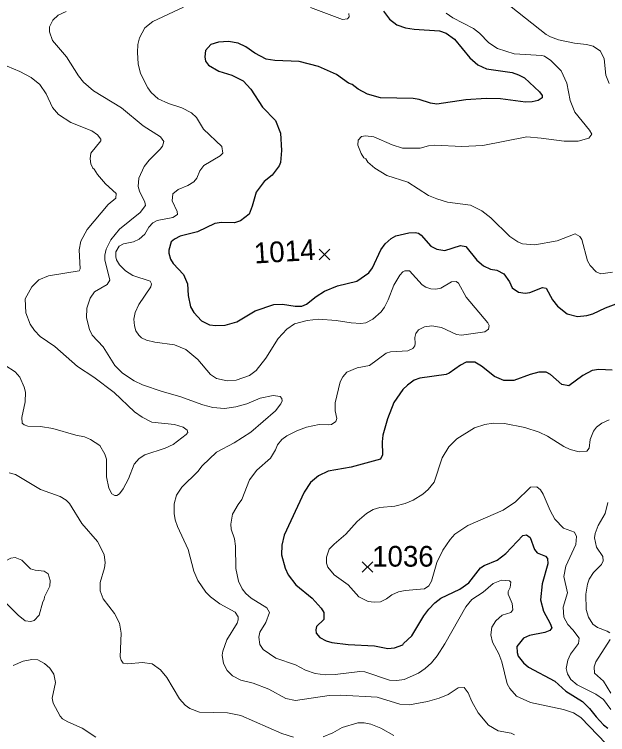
# Model space of a CAD drawing. Extents: x 265 to 291.4, y 7731.5 to 7759.6.
# Drawn here: x 274.669 to 276.962, y 7743.498 to 7746.284 of the extents above; entities that cross this region are included whole.
import ezdxf
from ezdxf.enums import TextEntityAlignment as Align

# ---------------------------------------------------------------- set-up
doc = ezdxf.new("R2010")
doc.units = 0
doc.header["$LTSCALE"] = 0.032
for name, color, linetype, lineweight in [('1', 7, 'Continuous', 25), ('2', 7, 'Continuous', 13), ('21', 7, 'Continuous', 25), ('61', 7, 'Continuous', 13)]:
    doc.layers.add(name, color=color, linetype=linetype, lineweight=lineweight)

msp = doc.modelspace()

# ---------------------------------------------------------------- linework, layer by layer
at = {"layer": '1'}
for points in [[(276.0961, 7746.2963), (276.1183, 7746.2653), (276.147, 7746.2438)], [(276.147, 7746.2438), (276.1804, 7746.2319), (276.2138, 7746.2263), (276.3125, 7746.2207), (276.3379, 7746.2112), (276.3705, 7746.1873), (276.4294, 7746.115)], [(276.4294, 7746.115), (276.4604, 7746.0887), (276.4939, 7746.0736), (276.5925, 7746.0585), (276.6179, 7746.0505), (276.6402, 7746.0378), (276.6991, 7745.9845), (276.7086, 7745.9702), (276.7086, 7745.9614), (276.6935, 7745.9503), (276.6705, 7745.9455), (276.645, 7745.9447), (276.5479, 7745.9574), (276.4923, 7745.959), (276.4143, 7745.9535), (276.3013, 7745.9367), (276.2775, 7745.9399), (276.2329, 7745.9551), (276.2107, 7745.959), (276.0834, 7745.9614), (276.0333, 7745.9749), (275.9975, 7745.9948), (275.9744, 7746.0123), (275.9609, 7746.0179), (275.9139, 7746.0513), (275.8447, 7746.0823), (275.77, 7746.1014), (275.6761, 7746.1054), (275.6427, 7746.111), (275.5981, 7746.134), (275.5639, 7746.1587), (275.5345, 7746.173), (275.4963, 7746.1786), (275.4581, 7746.1762), (275.4287, 7746.1675), (275.408, 7746.1436), (275.4048, 7746.1197), (275.4072, 7746.103), (275.4191, 7746.0879), (275.4597, 7746.064), (275.509, 7746.0489), (275.5536, 7746.0266), (275.583, 7745.994), (275.6275, 7745.9248), (275.6777, 7745.8739), (275.6976, 7745.8238), (275.7015, 7745.757), (275.6976, 7745.7109), (275.692, 7745.6981), (275.665, 7745.6623), (275.6339, 7745.6376), (275.6029, 7745.5955), (275.5886, 7745.5422), (275.5766, 7745.5112), (275.5432, 7745.4857), (275.5202, 7745.4778), (275.4693, 7745.4794), (275.4438, 7745.4754), (275.377, 7745.4428), (275.3102, 7745.4261), (275.2879, 7745.4149), (275.2752, 7745.4046), (275.2656, 7745.372), (275.2656, 7745.3608), (275.272, 7745.337), (275.2823, 7745.3203), (275.3229, 7745.2781), (275.338, 7745.2415), (275.3412, 7745.197), (275.3499, 7745.1524), (275.3626, 7745.1302), (275.3921, 7745.0983), (275.4231, 7745.0832), (275.447, 7745.0808), (275.4836, 7745.0824), (275.5281, 7745.0951), (275.5997, 7745.1373), (275.6713, 7745.1612), (275.7047, 7745.1635), (275.7541, 7745.1548), (275.7795, 7745.1548), (275.7986, 7745.1635), (275.8352, 7745.193), (275.8678, 7745.2137), (275.9179, 7745.2335), (275.9919, 7745.2518), (276.0388, 7745.2837), (276.0531, 7745.3036), (276.0857, 7745.3736), (276.1017, 7745.3966), (276.1255, 7745.4173), (276.1438, 7745.4269), (276.1932, 7745.4388), (276.2186, 7745.4404), (276.2313, 7745.4372)], [(276.2313, 7745.4372), (276.2417, 7745.4292), (276.2783, 7745.3879), (276.3013, 7745.3751), (276.3324, 7745.3704), (276.3936, 7745.3895), (276.4135, 7745.3855)], [(276.4135, 7745.3855), (276.4564, 7745.333), (276.4819, 7745.3115), (276.5098, 7745.2988), (276.5336, 7745.294), (276.5607, 7745.2805), (276.5821, 7745.2495), (276.5925, 7745.2264), (276.6179, 7745.2097), (276.6434, 7745.2049), (276.6609, 7745.2081), (276.7102, 7745.2272), (276.7237, 7745.2248), (276.7484, 7745.1795), (276.7683, 7745.1548), (276.8057, 7745.1262), (276.8455, 7745.1158), (276.8821, 7745.119), (276.9043, 7745.1254), (276.9536, 7745.1492), (277.0046, 7745.1675)], [(276.9791, 7744.9074), (276.9282, 7744.9106), (276.9027, 7744.9058), (276.8661, 7744.8867), (276.812, 7744.8469), (276.785, 7744.8517), (276.7412, 7744.8915), (276.7237, 7744.9002), (276.6959, 7744.9002), (276.6625, 7744.8915), (276.5989, 7744.8676), (276.5607, 7744.8676), (276.5241, 7744.8835), (276.4739, 7744.9233), (276.4485, 7744.9384), (276.4151, 7744.9384), (276.3936, 7744.9273), (276.3499, 7744.8963), (276.3379, 7744.8915), (276.2361, 7744.8772), (276.2146, 7744.8692), (276.1884, 7744.8501), (276.1709, 7744.8326), (276.1359, 7744.7833), (276.1112, 7744.7197), (276.0929, 7744.656), (276.0905, 7744.6306), (276.0921, 7744.5797), (276.0834, 7744.5629), (275.9704, 7744.5327), (275.8813, 7744.5176), (275.8439, 7744.4993), (275.8137, 7744.4731), (275.789, 7744.4365), (275.7119, 7744.2694), (275.7023, 7744.2313), (275.7015, 7744.1931), (275.7151, 7744.1422), (275.727, 7744.1167), (275.7564, 7744.0769), (275.8193, 7744.026), (275.8542, 7743.9878), (275.8654, 7743.9711), (275.8654, 7743.9441), (275.8368, 7743.917), (275.8336, 7743.9035), (275.8352, 7743.8908), (275.8495, 7743.8741), (275.8734, 7743.8605), (275.8957, 7743.8542)], [(276.1725, 7743.8502), (276.2051, 7743.8804), (276.2512, 7743.9576), (276.2703, 7743.9839), (276.2934, 7744.0085), (276.3173, 7744.026), (276.3904, 7744.061), (276.4254, 7744.0857), (276.4708, 7744.143), (276.4843, 7744.1525), (276.5352, 7744.1724), (276.5686, 7744.1986), (276.6346, 7744.2678), (276.6482, 7744.271), (276.6625, 7744.2607), (276.679, 7744.2143), (276.6896, 7744.2011), (276.7221, 7744.1884), (276.7301, 7744.1791), (276.7308, 7744.1592), (276.7094, 7744.0817), (276.7022, 7744.0197), (276.7134, 7743.9751), (276.7404, 7743.9274), (276.746, 7743.9115), (276.7388, 7743.9003), (276.7198, 7743.8931), (276.6593, 7743.8812), (276.6362, 7743.8709), (276.6116, 7743.8391), (276.6124, 7743.816), (276.6163, 7743.8017), (276.6362, 7743.7754), (276.6561, 7743.7587), (276.758, 7743.7054), (276.8009, 7743.6664), (276.8646, 7743.6267), (276.8924, 7743.5996), (276.917, 7743.567), (276.9457, 7743.536), (276.9632, 7743.5233)], [(275.8957, 7743.8542), (275.9593, 7743.847), (276.0611, 7743.8422), (276.112, 7743.8319), (276.1375, 7743.8343), (276.1709, 7743.8454), (276.1725, 7743.8502)]]:
    msp.add_lwpolyline(points, dxfattribs=at)
at = {"layer": '2'}
for points in [[(275.3229, 7746.3114), (275.2036, 7746.2566), (275.1733, 7746.2311), (275.1527, 7746.1929), (275.1463, 7746.1675), (275.1447, 7746.1357), (275.1479, 7746.0927), (275.1558, 7746.0545), (275.1845, 7745.9996), (275.1972, 7745.9813), (275.2243, 7745.9567), (275.264, 7745.9392), (275.3165, 7745.9225), (275.3539, 7745.9034), (275.3722, 7745.8843), (275.4, 7745.8397), (275.4701, 7745.7721), (275.474, 7745.7467), (275.4645, 7745.7363), (275.4016, 7745.6997), (275.3857, 7745.679), (275.3738, 7745.6504), (275.3619, 7745.6361), (275.3396, 7745.6218), (275.3022, 7745.6066), (275.2807, 7745.5891), (275.2791, 7745.5629), (275.2982, 7745.5215), (275.299, 7745.5096), (275.2815, 7745.4977), (275.2211, 7745.4865), (275.2036, 7745.4778), (275.1892, 7745.4611), (275.1725, 7745.434), (275.1511, 7745.4141), (275.1288, 7745.4046), (275.0906, 7745.3958), (275.0739, 7745.3871), (275.0612, 7745.3656), (275.0604, 7745.3465), (275.0636, 7745.3338), (275.0747, 7745.3147), (275.0978, 7745.2916), (275.1272, 7745.2741), (275.1932, 7745.2519), (275.1988, 7745.2415), (275.1964, 7745.2296), (275.1503, 7745.162), (275.1359, 7745.1302), (275.1312, 7745.1047), (275.1328, 7745.0792), (275.1383, 7745.0602), (275.1495, 7745.0426), (275.1606, 7745.0331), (275.1797, 7745.0236), (275.2115, 7745.0156), (275.2879, 7745.0053), (275.3316, 7744.9878), (275.3786, 7744.9496), (275.4271, 7744.8915), (275.4502, 7744.8756), (275.4915, 7744.866), (275.5265, 7744.8692), (275.5775, 7744.8867), (275.6037, 7744.9058), (275.6411, 7744.9536), (275.688, 7745.0299), (275.7222, 7745.0657), (275.7517, 7745.0864), (275.8002, 7745.0999), (275.8447, 7745.1047), (275.9132, 7745.0999), (275.9704, 7745.0904), (276.0086, 7745.0888), (276.0277, 7745.0912), (276.0547, 7745.1055), (276.0866, 7745.1333), (276.0993, 7745.1508), (276.1136, 7745.1795)], [(275.9617, 7746.2868), (275.9625, 7746.2741), (275.9561, 7746.2661), (275.937, 7746.2645), (275.8129, 7746.3106)], [(276.5885, 7746.313), (276.7245, 7746.2064), (276.7405, 7746.1969), (276.7723, 7746.1858), (276.8343, 7746.173), (276.8805, 7746.1675), (276.9059, 7746.1603), (276.9338, 7746.142), (276.9481, 7746.1118), (276.9552, 7746.0481), (276.9679, 7746.0163)], [(275.4629, 7744.0045), (275.4263, 7744.0308), (275.4088, 7744.0491), (275.3786, 7744.0944), (275.3627, 7744.131), (275.3404, 7744.2138), (275.299, 7744.3029), (275.2903, 7744.3283), (275.2863, 7744.3538), (275.2863, 7744.3904), (275.295, 7744.4238), (275.3157, 7744.4556), (275.3778, 7744.5152), (275.3945, 7744.5375), (275.4502, 7744.59), (275.5186, 7744.6266), (275.5822, 7744.668), (275.6785, 7744.7507), (275.6992, 7744.777), (275.7039, 7744.7897), (275.7023, 7744.7984), (275.696, 7744.8064), (275.6697, 7744.8104), (275.6188, 7744.7992), (275.5679, 7744.777), (275.525, 7744.7658), (275.4804, 7744.7594), (275.4359, 7744.7634), (275.3977, 7744.7738), (275.3086, 7744.8064), (275.2402, 7744.8247), (275.1638, 7744.8509), (275.132, 7744.8668), (275.0874, 7744.8955), (275.0572, 7744.9257), (275.0119, 7744.9981), (274.9697, 7745.0434), (274.9586, 7745.0649), (274.9474, 7745.1095), (274.949, 7745.1477), (274.9617, 7745.1858), (274.9784, 7745.2113), (275.0278, 7745.2391), (275.0381, 7745.2558), (275.019, 7745.3338), (275.019, 7745.3529), (275.0238, 7745.3759), (275.0413, 7745.4118), (275.0747, 7745.4531), (275.155, 7745.5175), (275.1757, 7745.5446), (275.1733, 7745.5573), (275.1519, 7745.5995), (275.1479, 7745.6186), (275.1495, 7745.6504), (275.171, 7745.695), (275.19, 7745.7196), (275.233, 7745.7618), (275.2418, 7745.7745), (275.2465, 7745.792), (275.2338, 7745.8103), (275.167, 7745.8532), (275.0827, 7745.9225), (274.9753, 7745.9877), (274.9363, 7746.0219), (274.9164, 7746.0466), (274.8703, 7746.1197), (274.8162, 7746.1826), (274.8042, 7746.2168), (274.805, 7746.2359), (274.817, 7746.2613), (274.8384, 7746.2812), (274.8695, 7746.2947)], [(276.3427, 7745.5573), (276.3013, 7745.57), (276.2695, 7745.5836), (276.19, 7745.6353), (276.1088, 7745.6607), (276.0627, 7745.6886), (276.0356, 7745.7124), (276.0277, 7745.7244), (276.0197, 7745.7291), (276.0094, 7745.7459), (275.9967, 7745.7777), (275.9975, 7745.7976), (276.011, 7745.8111), (276.0261, 7745.8143), (276.0579, 7745.8103), (276.1287, 7745.7793), (276.1693, 7745.7665), (276.2377, 7745.7665), (276.2695, 7745.7753), (276.2934, 7745.7777), (276.3984, 7745.7729), (276.4795, 7745.7761), (276.6498, 7745.8095), (276.7055, 7745.8055), (276.7945, 7745.7936), (276.8486, 7745.7928), (276.8892, 7745.8055), (276.9003, 7745.8206), (276.8916, 7745.8365), (276.8351, 7745.905), (276.8168, 7745.9511), (276.8041, 7746.0179), (276.7826, 7746.0656), (276.7428, 7746.1054), (276.7174, 7746.1221), (276.707, 7746.1253), (276.6004, 7746.1317), (276.5368, 7746.1516), (276.5026, 7746.1738), (276.4668, 7746.2104), (276.4429, 7746.2287), (276.3634, 7746.2701), (276.3379, 7746.2884)], [(274.6165, 7746.0943), (274.6897, 7746.0625), (274.7342, 7746.0394), (274.7677, 7746.0123), (274.7923, 7745.9766), (274.8162, 7745.9241), (274.8392, 7745.8962), (274.887, 7745.866), (274.9681, 7745.8334), (274.9904, 7745.8182), (275.0031, 7745.8007), (275.0031, 7745.7944), (274.9649, 7745.7466), (274.9617, 7745.7252), (274.9649, 7745.7053), (274.9721, 7745.6886), (274.9777, 7745.6846), (274.9896, 7745.6639), (275.0206, 7745.6289), (275.0628, 7745.5907), (275.0612, 7745.5732), (275.0318, 7745.5486), (274.9498, 7745.4515), (274.9251, 7745.407), (274.9188, 7745.3736), (274.9236, 7745.2996), (274.9196, 7745.2916), (274.8011, 7745.2725), (274.7629, 7745.2574), (274.7358, 7745.2304), (274.7112, 7745.1834), (274.7136, 7745.1294), (274.7295, 7745.0856), (274.7461, 7745.0617), (274.7684, 7745.0379), (274.8249, 7744.9989), (274.9124, 7744.9225), (274.9761, 7744.8804), (275.054, 7744.8215), (275.1336, 7744.7467)], [(276.6323, 7745.3966), (276.6148, 7745.4046), (276.5837, 7745.4253), (276.5106, 7745.4969), (276.4756, 7745.5239), (276.4318, 7745.5462), (276.3427, 7745.5573)], [(276.9807, 7745.2861), (276.9361, 7745.2805), (276.9178, 7745.2884), (276.894, 7745.3123), (276.8844, 7745.3306), (276.8622, 7745.4134), (276.8542, 7745.4245), (276.8359, 7745.4348), (276.7675, 7745.4078), (276.68, 7745.3927), (276.6323, 7745.3966)], [(276.1136, 7745.1795), (276.1351, 7745.2368), (276.1589, 7745.2749), (276.1709, 7745.2885), (276.178, 7745.2916), (276.1963, 7745.2916), (276.2449, 7745.2383)], [(276.2449, 7745.2383), (276.2592, 7745.2288), (276.2791, 7745.2224), (276.2982, 7745.2208), (276.3173, 7745.2248), (276.3586, 7745.2495), (276.3761, 7745.2503), (276.3849, 7745.2439), (276.4151, 7745.1906), (276.4986, 7745.0904), (276.5034, 7745.0808), (276.501, 7745.0657), (276.4875, 7745.0562), (276.3968, 7745.0426), (276.3777, 7745.0458), (276.3204, 7745.0721), (276.2823, 7745.0792), (276.2536, 7745.0753), (276.2305, 7745.0641), (276.2202, 7745.049), (276.217, 7745.0339), (276.2186, 7745.0108), (276.2162, 7745.0013), (276.209, 7744.9917), (276.19, 7744.983), (276.1232, 7744.9782), (276.1057, 7744.9734), (276.042, 7744.9257), (275.9943, 7744.9162), (275.9537, 7744.8995), (275.9386, 7744.8819), (275.9283, 7744.8629), (275.9084, 7744.7809), (275.9092, 7744.7499), (275.9147, 7744.7213), (275.9116, 7744.7093), (275.8941, 7744.6982), (275.8845, 7744.6958), (275.8463, 7744.6982), (275.7986, 7744.6871), (275.7604, 7744.6727), (275.7222, 7744.6536), (275.7031, 7744.6393), (275.6856, 7744.6187), (275.6785, 7744.5996), (275.6594, 7744.567), (275.6061, 7744.5208), (275.5774, 7744.4842), (275.548, 7744.4079), (275.5337, 7744.3888), (275.5122, 7744.3506), (275.5059, 7744.3124), (275.5074, 7744.2933), (275.5194, 7744.2551), (275.5241, 7744.2265), (275.5249, 7744.1406), (275.5353, 7744.0913), (275.5496, 7744.0626), (275.5639, 7744.0435), (275.5838, 7744.026), (275.6442, 7743.9886), (275.6554, 7743.9703), (275.6411, 7743.9322), (275.618, 7743.894), (275.6132, 7743.8749), (275.618, 7743.8462), (275.6307, 7743.8272), (275.6793, 7743.7937), (275.7556, 7743.7683), (275.7938, 7743.7476), (275.832, 7743.7349), (275.8702, 7743.7301), (275.9084, 7743.7309), (276.0038, 7743.7428), (276.0229, 7743.7412), (276.1184, 7743.7094), (276.147, 7743.7078), (276.1757, 7743.711), (276.2313, 7743.7365), (276.2568, 7743.754), (276.2807, 7743.7754), (276.3029, 7743.8033), (276.3324, 7743.8494), (276.4135, 7743.9926), (276.4374, 7744.0205), (276.4811, 7744.0491), (276.5193, 7744.0825), (276.5511, 7744.0952), (276.5829, 7744.0936), (276.5877, 7744.0873), (276.5853, 7744.0666), (276.5774, 7744.0515), (276.5774, 7744.0419), (276.5933, 7744.0053), (276.5949, 7743.9807)], [(275.3388, 7744.6672), (275.3332, 7744.6584), (275.2831, 7744.6202), (275.2513, 7744.6059), (275.1734, 7744.5797), (275.1511, 7744.5661), (275.132, 7744.5439), (275.1097, 7744.4874), (275.0898, 7744.4492), (275.0755, 7744.4301), (275.0644, 7744.423), (275.0572, 7744.423), (275.0461, 7744.4293), (275.0341, 7744.4508), (275.0254, 7744.4954), (275.0254, 7744.5638), (275.019, 7744.5829), (274.9991, 7744.6163), (274.9633, 7744.6401), (274.9395, 7744.6497), (274.9061, 7744.656), (274.817, 7744.6815), (274.7692, 7744.6895), (274.7215, 7744.6918), (274.7072, 7744.6958), (274.6992, 7744.7022), (274.6976, 7744.7245), (274.7104, 7744.7849), (274.712, 7744.8231), (274.7072, 7744.8422), (274.6897, 7744.8804), (274.6714, 7744.9011), (274.6316, 7744.9273)], [(275.1336, 7744.7467), (275.1622, 7744.726), (275.2004, 7744.707), (275.2879, 7744.6982), (275.3213, 7744.6879), (275.3364, 7744.6759), (275.3388, 7744.6672)], [(276.9743, 7743.5949), (276.9465, 7743.6346), (276.9163, 7743.6553), (276.8439, 7743.6903), (276.82, 7743.7118), (276.8065, 7743.7333), (276.8017, 7743.754), (276.8081, 7743.7858), (276.8184, 7743.8097), (276.8494, 7743.8502), (276.8518, 7743.8709), (276.8279, 7743.9035), (276.8081, 7743.9242), (276.7921, 7743.9528), (276.7898, 7743.991), (276.8065, 7744.0467), (276.7929, 7744.1103), (276.8001, 7744.1501), (276.8391, 7744.2329), (276.8415, 7744.2647), (276.8335, 7744.2814), (276.7914, 7744.2973), (276.7579, 7744.3315), (276.7396, 7744.3649), (276.7126, 7744.4285), (276.7023, 7744.4445), (276.6887, 7744.4564), (276.6641, 7744.4556), (276.6052, 7744.3983), (276.5575, 7744.3657), (276.4214, 7744.3068), (276.3713, 7744.2734), (276.353, 7744.2527), (276.3252, 7744.2122), (276.3021, 7744.1644), (276.2814, 7744.0913), (276.2703, 7744.0737), (276.2536, 7744.0626), (276.1788, 7744.0562), (276.1534, 7744.0499), (276.1279, 7744.0387), (276.1072, 7744.0236), (276.0834, 7744.0117), (276.0595, 7744.0101), (276.0357, 7744.0133), (276.0007, 7744.0316), (275.9585, 7744.0777), (275.9052, 7744.1159), (275.8805, 7744.1453), (275.8757, 7744.1613), (275.875, 7744.1851), (275.8861, 7744.2154), (275.9044, 7744.2352), (275.9497, 7744.2734), (275.9943, 7744.3219), (276.0293, 7744.3538), (276.0563, 7744.3689), (276.0818, 7744.376), (276.1391, 7744.3824), (276.1788, 7744.3927), (276.2107, 7744.4055), (276.2473, 7744.4285), (276.2679, 7744.446), (276.291, 7744.4747), (276.3228, 7744.5685), (276.3483, 7744.6107), (276.3785, 7744.6425), (276.4477, 7744.6847), (276.4875, 7744.6982), (276.5193, 7744.703), (276.5639, 7744.7014), (276.6418, 7744.6863), (276.6975, 7744.668), (276.7293, 7744.6528), (276.793, 7744.6123), (276.8176, 7744.6011)], [(276.9186, 7744.6871), (276.9393, 7744.703), (276.968, 7744.7157)], [(276.8176, 7744.6011), (276.8518, 7744.5924), (276.8821, 7744.5948), (276.8908, 7744.6067), (276.8948, 7744.6401), (276.9067, 7744.672), (276.9186, 7744.6871)], [(274.6483, 7744.5113), (274.6738, 7744.5041), (274.7692, 7744.446), (274.8456, 7744.419), (274.8687, 7744.4047), (274.8814, 7744.3919), (274.9291, 7744.3148), (274.9904, 7744.2456)], [(276.9624, 7744.3959), (276.9528, 7744.3538), (276.9258, 7744.3076), (276.9131, 7744.2758), (276.9115, 7744.2599), (276.9194, 7744.2233), (276.9433, 7744.1867), (276.9449, 7744.1708), (276.9385, 7744.1565), (276.9067, 7744.1255), (276.8908, 7744.0992), (276.8844, 7744.0801), (276.8781, 7744.0419), (276.8789, 7743.9815), (276.8876, 7743.9528), (276.9043, 7743.9258), (276.9234, 7743.913), (276.96, 7743.8987), (276.9703, 7743.8916)], [(274.9904, 7744.2456), (275.0158, 7744.1947), (275.0198, 7744.1628), (275.0174, 7744.1438), (274.9999, 7744.0865), (274.9999, 7744.0547), (275.0119, 7744.0228)], [(275.0119, 7744.0228), (275.0564, 7743.9672), (275.0747, 7743.929), (275.0811, 7743.8908), (275.0779, 7743.7985), (275.0811, 7743.7858), (275.0898, 7743.7746), (275.1065, 7743.7715), (275.1638, 7743.7778), (275.202, 7743.7715), (275.2338, 7743.7484), (275.2577, 7743.719), (275.307, 7743.6362), (275.3285, 7743.6124), (275.3468, 7743.5988), (275.3849, 7743.5853), (275.4931, 7743.5821), (275.544, 7743.5726), (275.7031, 7743.5026), (275.7477, 7743.4883)], [(275.474, 7743.8208), (275.4899, 7743.8653), (275.5305, 7743.929), (275.5345, 7743.9417), (275.5337, 7743.9544), (275.5218, 7743.9719), (275.4629, 7744.0045)], [(276.5949, 7743.9807), (276.5877, 7743.9711), (276.5543, 7743.96), (276.5304, 7743.9385), (276.5145, 7743.9138), (276.5105, 7743.8844), (276.5169, 7743.8558)], [(276.9711, 7743.8661), (276.9162, 7743.7794), (276.9099, 7743.7603), (276.9115, 7743.7357), (276.9465, 7743.7054), (276.9743, 7743.6585)], [(276.5169, 7743.8558), (276.5416, 7743.8112), (276.5535, 7743.7794), (276.5742, 7743.6951), (276.5837, 7743.676), (276.6092, 7743.6474), (276.6641, 7743.6227), (276.7914, 7743.5957), (276.8295, 7743.5829), (276.8582, 7743.5646), (276.9568, 7743.4628), (277.0046, 7743.4461)], [(276.602, 7743.497), (276.5893, 7743.5034), (276.5384, 7743.5129), (276.5018, 7743.5344), (276.4612, 7743.5821), (276.4366, 7743.6259), (276.423, 7743.6601), (276.4079, 7743.68), (276.3841, 7743.6792), (276.3459, 7743.6537), (276.3109, 7743.6386), (276.2663, 7743.6259), (276.1963, 7743.614), (276.1582, 7743.6163), (276.0707, 7743.6426), (275.9307, 7743.6505), (275.8861, 7743.6497), (275.7556, 7743.6299), (275.7175, 7743.6378), (275.653, 7743.6744), (275.5918, 7743.6975), (275.544, 7743.7094), (275.5122, 7743.7261), (275.4915, 7743.7468), (275.4772, 7743.7731), (275.4724, 7743.8049), (275.474, 7743.8208)], [(274.984, 7743.4883), (274.9315, 7743.5233), (274.875, 7743.5471), (274.8551, 7743.5599), (274.8464, 7743.5694), (274.8186, 7743.6203), (274.8154, 7743.6394), (274.8273, 7743.6999), (274.8217, 7743.7325), (274.8058, 7743.7556), (274.7859, 7743.7739), (274.7597, 7743.7874), (274.7358, 7743.789), (274.7024, 7743.7818), (274.6642, 7743.7659)], [(275.8622, 7743.4899), (275.9004, 7743.5058), (275.9354, 7743.5257), (275.9959, 7743.544), (276.0213, 7743.544), (276.0468, 7743.5384), (276.085, 7743.5233), (276.1359, 7743.4954)]]:
    msp.add_lwpolyline(points, dxfattribs=at)
msp.add_lwpolyline([(274.6046, 7744.141), (274.6117, 7744.1533), (274.6308, 7744.1684), (274.6547, 7744.1803), (274.6722, 7744.1835), (274.6977, 7744.1732), (274.7311, 7744.1398), (274.7486, 7744.1342), (274.7836, 7744.1302), (274.7995, 7744.1199), (274.8074, 7744.0944), (274.8058, 7744.073), (274.7851, 7744.0308), (274.7843, 7744.0204), (274.7788, 7744.0117), (274.7653, 7743.9608), (274.7454, 7743.9393), (274.7327, 7743.9353), (274.7112, 7743.9385), (274.6833, 7743.96), (274.6268, 7744.0165), (274.6085, 7744.0388), (274.5974, 7744.0706), (274.5958, 7744.096)], close=True, dxfattribs=at)
at = {"layer": '21'}
for p, q in [((275.8474, 7745.3762), (275.8886, 7745.335)), ((275.8886, 7745.3762), (275.8474, 7745.335)), ((276.0132, 7744.1671), (276.0544, 7744.1259)), ((276.0544, 7744.1671), (276.0132, 7744.1259))]:
    msp.add_line(p, q, dxfattribs=at)

# ---------------------------------------------------------------- texts
at = {"layer": '61'}
msp.add_text('1014', height=0.08, rotation=3.563, dxfattribs=at).set_placement((275.7159, 7745.3273), align=Align.CENTER)
msp.add_text('1036', height=0.08, dxfattribs=at).set_placement((276.1707, 7744.1479), align=Align.CENTER)

doc.saveas('drawing.dxf')
